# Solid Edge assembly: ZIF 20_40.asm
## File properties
Title: Zylinder
Author: bmolnar
Template: iso metric assembly.asm
Last saved by: bmolnar
Revision: 17
Application: Solid Edge
Username: bmolnar
Dokumentum tartalom típus: 1
Document Number: ZIF 20/40
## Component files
Mutter.par
Profilrohr.par
Kolbenstange.par
Kit_2.par
Kit_1.par
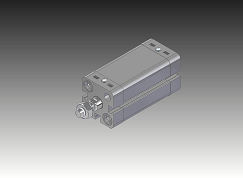
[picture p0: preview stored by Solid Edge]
